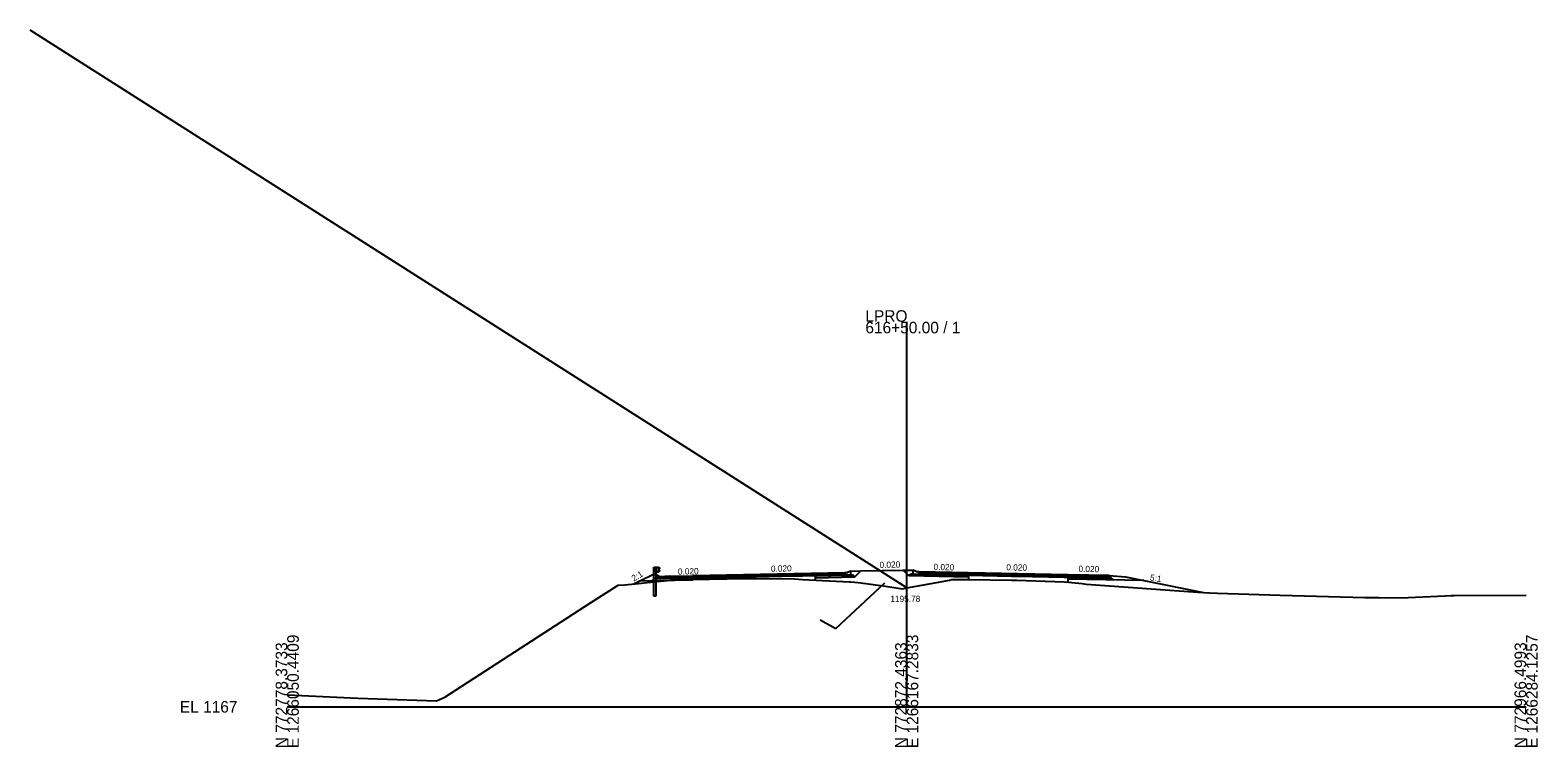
# Model space of a CAD drawing. Extents: x -3833 to 1267678, y -522 to 773248.
# Drawn here: x 1937.8 to 2302.8, y 7490.3 to 7663.8 of the extents above; entities that cross this region are included whole.
import ezdxf

# ---------------------------------------------------------------- set-up
doc = ezdxf.new("R2010")
doc.units = 0
for name, color, linetype in [('Exist Cross Section Cell', 7, 'Continuous'), ('Exist XS Center Line Elevation Label', 7, 'Continuous'), ('Exist XS Ground Line', 7, 'Continuous'), ('Prop CMT DNC', 7, 'Continuous'), ('Prop CMT Guardrail Graphics', 7, 'Continuous'), ('Prop CMT Pvmt Course 1', 7, 'Continuous'), ('Prop CMT Pvmt Course 2', 7, 'Continuous'), ('Prop CMT Pvmt Course 3', 7, 'Continuous'), ('Prop CMT Pvmt Course 4', 7, 'Continuous'), ('Prop CMT Shld Paved Course 1', 7, 'Continuous'), ('Prop CMT Shld Paved Course 2', 7, 'Continuous'), ('Prop CMT Shld Paved Course 4', 7, 'Continuous'), ('Prop CMT Slope Grass', 7, 'Continuous'), ('Prop CMT Subgrade Earthwork', 7, 'Continuous'), ('Prop Conc Curb and Gutter', 7, 'Continuous'), ('Prop Conc Island Cover', 7, 'Continuous'), ('Prop Corridor Mesh Bottom', 7, 'Continuous'), ('Prop XS Ditch Slope Text', 7, 'Continuous'), ('Prop XS Finish Grade', 7, 'Continuous'), ('Prop XS SE Text', 7, 'Continuous'), ('Scratch_Level_1', 7, 'Continuous'), ('Scratch_Level_5', 7, 'Continuous'), ('Typical Curb CELL', 7, 'Continuous')]:
    doc.layers.add(name, color=color, linetype=linetype)

msp = doc.modelspace()

# ---------------------------------------------------------------- linework, layer by layer
at = {"layer": 'Exist Cross Section Cell'}
for p, q in [((2150, 7500), (2150, 7593.23)), ((2000, 7500), (2150, 7500)), ((2150, 7500), (2300, 7500))]:
    msp.add_line(p, q, dxfattribs=at)
at = {"layer": 'Exist XS Ground Line'}
for p, q in [((2073.43, 7525.14), (2080.16, 7529.42)), ((2080.16, 7529.42), (2081.75, 7529.55)), ((2081.75, 7529.55), (2085.06, 7529.88)), ((2085.06, 7529.88), (2087.18, 7530.1)), ((2087.18, 7530.1), (2093.69, 7530.75)), ((2093.69, 7530.75), (2096.2, 7530.83)), ((2096.2, 7530.83), (2098.17, 7530.86)), ((2098.17, 7530.86), (2110.53, 7531.06)), ((2110.53, 7531.06), (2111.14, 7531.08)), ((2111.14, 7531.08), (2113.57, 7531.05)), ((2113.57, 7531.05), (2122.82, 7530.96)), ((2122.82, 7530.96), (2124.76, 7530.86)), ((2124.76, 7530.86), (2136.12, 7530.3)), ((2136.12, 7530.3), (2136.49, 7530.27)), ((2136.49, 7530.27), (2138.27, 7530.12)), ((2138.27, 7530.12), (2138.92, 7530)), ((2138.92, 7530), (2144.84, 7529.18)), ((2144.84, 7529.18), (2149.02, 7528.6)), ((2149.02, 7528.6), (2150, 7528.78)), ((2150, 7528.78), (2155.92, 7529.86)), ((2155.92, 7529.86), (2160.39, 7530.66)), ((2160.39, 7530.66), (2160.97, 7530.81)), ((2160.97, 7530.81), (2164.4, 7530.82)), ((2164.4, 7530.82), (2165, 7530.81)), ((2165, 7530.81), (2175.41, 7530.68)), ((2175.41, 7530.68), (2176.71, 7530.67)), ((2176.71, 7530.67), (2188.12, 7530.23)), ((2188.12, 7530.23), (2189.3, 7530.19)), ((2189.3, 7530.19), (2190.01, 7530.12)), ((2190.01, 7530.12), (2192.48, 7529.87)), ((2192.48, 7529.87), (2193.5, 7529.68)), ((2193.5, 7529.68), (2220.48, 7527.76)), ((2038.15, 7502.36), (2073.43, 7525.14)), ((2220.48, 7527.76), (2223.36, 7527.58)), ((2223.36, 7527.58), (2225.3, 7527.54)), ((2225.3, 7527.54), (2240.43, 7527.06)), ((2240.43, 7527.06), (2260.94, 7526.45)), ((2260.94, 7526.45), (2264.36, 7526.44)), ((2264.36, 7526.44), (2269.66, 7526.36)), ((2269.66, 7526.36), (2280.42, 7526.84)), ((2280.42, 7526.84), (2281.81, 7526.92)), ((2281.81, 7526.92), (2282.57, 7526.96)), ((2282.57, 7526.96), (2300, 7527.06)), ((2000, 7502.87), (2003.55, 7502.7)), ((2003.55, 7502.7), (2017.11, 7502.13)), ((2017.11, 7502.13), (2036.18, 7501.46)), ((2036.18, 7501.46), (2038.15, 7502.36))]:
    msp.add_line(p, q, dxfattribs=at)
at = {"layer": 'Prop CMT Guardrail Graphics'}
for p, q in [((2088.79, 7531.32), (2088.79, 7533.82)), ((2088.79, 7533.82), (2089.27, 7533.82)), ((2089.27, 7532.64), (2089.27, 7533.82)), ((2089.27, 7533.82), (2089.94, 7533.82)), ((2089.27, 7533.82), (2089.27, 7531.31)), ((2089.94, 7532.64), (2089.27, 7532.64)), ((2089.94, 7533.82), (2089.94, 7532.64)), ((2089.94, 7533.74), (2090.04, 7533.72)), ((2089.94, 7532.72), (2089.94, 7533.74)), ((2089.94, 7533.74), (2089.94, 7533.74)), ((2089.94, 7533.74), (2089.94, 7533.74)), ((2090.04, 7532.74), (2089.94, 7532.72)), ((2090.18, 7533.48), (2089.95, 7533.27)), ((2089.95, 7533.27), (2089.95, 7533.27)), ((2089.95, 7533.27), (2089.95, 7533.18)), ((2089.95, 7533.18), (2089.95, 7533.18)), ((2089.95, 7533.18), (2090.18, 7532.98)), ((2090.04, 7533.72), (2090.04, 7533.72)), ((2090.04, 7533.72), (2090.18, 7533.62)), ((2090.18, 7532.84), (2090.04, 7532.74)), ((2090.04, 7532.7), (2090.04, 7532.7)), ((2090.18, 7533.62), (2090.18, 7533.62)), ((2090.18, 7533.62), (2090.18, 7533.48)), ((2090.18, 7533.48), (2090.18, 7533.48)), ((2090.18, 7532.98), (2090.18, 7532.84)), ((2090.18, 7532.95), (2090.18, 7532.95)), ((2090.18, 7532.8), (2090.18, 7532.8)), ((2088.79, 7526.81), (2088.79, 7531.32)), ((2089.27, 7531.31), (2089.27, 7526.81)), ((2089.27, 7526.81), (2088.79, 7526.81))]:
    msp.add_line(p, q, dxfattribs=at)
at = {"layer": 'Prop CMT Pvmt Course 1'}
for p, q in [((2135, 7532.45), (2098.21, 7531.71)), ((2098.21, 7531.46), (2135, 7532.2)), ((2135, 7532.2), (2135, 7532.45)), ((2135, 7532.2), (2135, 7532.2)), ((2189, 7531.97), (2165, 7532.45)), ((2165, 7532.45), (2165, 7532.2)), ((2165, 7532.2), (2165, 7532.2)), ((2189, 7531.72), (2189, 7531.97)), ((2189, 7531.97), (2189, 7531.97)), ((2098.21, 7531.46), (2111, 7531.72)), ((2098.21, 7531.71), (2098.21, 7531.71)), ((2098.21, 7531.71), (2098.21, 7531.46)), ((2098.21, 7531.46), (2098.21, 7531.46)), ((2189, 7531.72), (2189, 7531.72)), ((2189, 7531.72), (2189, 7531.72))]:
    msp.add_line(p, q, dxfattribs=at)
at = {"layer": 'Prop CMT Pvmt Course 2'}
for p, q in [((2135, 7532.2), (2135, 7532.2)), ((2135, 7532.2), (2135, 7531.87)), ((2135, 7531.87), (2135, 7531.87)), ((2135, 7531.87), (2135, 7531.86)), ((2135, 7531.86), (2135, 7531.86)), ((2165, 7532.2), (2153, 7532.44)), ((2153, 7532.1), (2165, 7531.86)), ((2165, 7532.2), (2165, 7532.2)), ((2165, 7531.86), (2165, 7531.86)), ((2165, 7531.86), (2165, 7531.86)), ((2165, 7531.86), (2165, 7531.86))]:
    msp.add_line(p, q, dxfattribs=at)
at = {"layer": 'Prop CMT Pvmt Course 3'}
for p, q in [((2137.01, 7531.9), (2135, 7531.86)), ((2137.46, 7531.45), (2137.01, 7531.9)), ((2150.7, 7531.86), (2150.99, 7532.14))]:
    msp.add_line(p, q, dxfattribs=at)
at = {"layer": 'Prop CMT Pvmt Course 4'}
for p, q in [((2127.86, 7532.3), (2127.86, 7530.71)), ((2135, 7531.86), (2135, 7531.87)), ((2135, 7531.86), (2135, 7531.86)), ((2150.99, 7532.14), (2150.54, 7531.7)), ((2151.49, 7532.13), (2150.99, 7532.14)), ((2165, 7531.4), (2165, 7531.86)), ((2165, 7531.86), (2165, 7531.86)), ((2165, 7531.86), (2165, 7531.86)), ((2137.46, 7531.45), (2127.86, 7531.26)), ((2165, 7531.03), (2165, 7531.03)), ((2165, 7531.03), (2165, 7531.03)), ((2165, 7531.03), (2165, 7531.03))]:
    msp.add_line(p, q, dxfattribs=at)
at = {"layer": 'Prop CMT Shld Paved Course 1'}
for p, q in [((2135, 7532.45), (2135, 7532.45)), ((2135, 7532.45), (2135, 7532.2)), ((2135, 7532.2), (2135, 7532.2)), ((2135, 7532.2), (2135, 7532.2)), ((2165, 7532.45), (2153, 7532.69)), ((2165, 7532.2), (2165, 7532.45)), ((2165, 7532.45), (2165, 7532.45)), ((2165, 7532.2), (2165, 7532.2)), ((2165, 7532.2), (2165, 7532.2)), ((2189, 7531.97), (2189, 7530.93)), ((2199, 7531.77), (2189, 7531.97)), ((2089.95, 7531.26), (2089.95, 7531.26)), ((2089.95, 7531.26), (2089.95, 7531.26)), ((2089.95, 7531.26), (2089.95, 7531.26)), ((2089.95, 7531.26), (2089.95, 7531.26)), ((2090.21, 7531.51), (2090.21, 7531.51)), ((2090.21, 7531.51), (2090.21, 7531.51)), ((2092.54, 7531.6), (2098.21, 7531.71)), ((2098.21, 7531.46), (2093.95, 7531.37)), ((2098.21, 7531.71), (2098.21, 7531.46)), ((2189, 7531.72), (2199.26, 7531.51)), ((2199.26, 7531.51), (2199, 7531.77))]:
    msp.add_line(p, q, dxfattribs=at)
at = {"layer": 'Prop CMT Shld Paved Course 2'}
for p, q in [((2113.57, 7531.77), (2122.82, 7531.95)), ((2122.82, 7531.95), (2124.76, 7531.99)), ((2122.82, 7531.95), (2122.82, 7531.95)), ((2124.76, 7531.99), (2135, 7532.2)), ((2124.76, 7531.99), (2124.76, 7531.99)), ((2135, 7531.86), (2124.76, 7531.66)), ((2135, 7532.2), (2135, 7532.2)), ((2135, 7532.2), (2135, 7531.86)), ((2135, 7531.86), (2135, 7531.86)), ((2135, 7531.86), (2135, 7531.86)), ((2175.41, 7531.99), (2165, 7532.2)), ((2165, 7532.2), (2165, 7532.2)), ((2165, 7532.2), (2165, 7532.2)), ((2165, 7532.2), (2165, 7532.2)), ((2165, 7532.2), (2165, 7531.86)), ((2165, 7531.86), (2165, 7531.86)), ((2165, 7531.86), (2165, 7531.86)), ((2165, 7531.86), (2165, 7531.86)), ((2165, 7531.86), (2165, 7531.86)), ((2165, 7531.86), (2175.41, 7531.65)), ((2176.71, 7531.96), (2175.41, 7531.99)), ((2175.41, 7531.99), (2175.41, 7531.99)), ((2188.12, 7531.73), (2176.71, 7531.96)), ((2176.71, 7531.96), (2176.71, 7531.96)), ((2089.61, 7530.92), (2089.61, 7530.92)), ((2089.61, 7530.92), (2089.61, 7530.92)), ((2089.61, 7530.92), (2089.61, 7530.92)), ((2089.61, 7530.92), (2089.61, 7530.92)), ((2089.95, 7531.26), (2089.95, 7531.26)), ((2089.95, 7531.26), (2089.95, 7531.26)), ((2092.54, 7531.35), (2098.21, 7531.46)), ((2098.21, 7531.13), (2092.54, 7531.01)), ((2098.21, 7531.46), (2111.14, 7531.72)), ((2098.21, 7531.13), (2098.21, 7531.46)), ((2098.21, 7531.46), (2098.21, 7531.13)), ((2111.14, 7531.39), (2098.21, 7531.13)), ((2098.21, 7531.13), (2098.21, 7531.13)), ((2111.14, 7531.72), (2113.57, 7531.77)), ((2111.14, 7531.72), (2111.14, 7531.72)), ((2113.57, 7531.43), (2111.14, 7531.39)), ((2111.14, 7531.39), (2111.14, 7531.39)), ((2113.57, 7531.77), (2113.57, 7531.77)), ((2122.82, 7531.62), (2113.57, 7531.43)), ((2113.57, 7531.43), (2113.57, 7531.43)), ((2124.76, 7531.66), (2122.82, 7531.62)), ((2122.82, 7531.62), (2122.82, 7531.62)), ((2124.76, 7531.66), (2124.76, 7531.66)), ((2175.41, 7531.65), (2175.41, 7531.65)), ((2175.41, 7531.65), (2176.71, 7531.63)), ((2176.71, 7531.63), (2176.71, 7531.63)), ((2176.71, 7531.63), (2188.12, 7531.4)), ((2189, 7531.72), (2188.12, 7531.73)), ((2188.12, 7531.73), (2188.12, 7531.73)), ((2188.12, 7531.4), (2188.12, 7531.4)), ((2188.12, 7531.4), (2189, 7531.38)), ((2199.26, 7531.51), (2189, 7531.72)), ((2189, 7531.39), (2199.59, 7531.17)), ((2189, 7531.38), (2189, 7531.38)), ((2199.59, 7531.17), (2199.26, 7531.51))]:
    msp.add_line(p, q, dxfattribs=at)
at = {"layer": 'Prop CMT Shld Paved Course 4'}
for p, q in [((2088.3, 7530.47), (2089.01, 7531.18)), ((2089.01, 7531.18), (2089.52, 7531.18)), ((2092.54, 7531.18), (2092.54, 7531.02)), ((2098.21, 7530.67), (2093.15, 7530.57)), ((2093.61, 7531.03), (2094.11, 7531.04)), ((2094.11, 7531.04), (2098.21, 7531.13)), ((2098.21, 7531.13), (2098.21, 7530.67)), ((2199.09, 7531.18), (2189, 7531.39)), ((2199.59, 7531.17), (2199.09, 7531.18)), ((2200.06, 7530.71), (2199.59, 7531.17))]:
    msp.add_line(p, q, dxfattribs=at)
at = {"layer": 'Prop CMT Slope Grass'}
for p, q in [((2085.23, 7530.41), (2088.82, 7532.21)), ((2088.82, 7532.21), (2089.52, 7531.86)), ((2136.51, 7532.88), (2138.92, 7532.92)), ((2149.16, 7533.08), (2151.49, 7533.12)), ((2199, 7531.77), (2203, 7531.45)), ((2203, 7531.45), (2207.43, 7530.56))]:
    msp.add_line(p, q, dxfattribs=at)
at = {"layer": 'Prop CMT Subgrade Earthwork'}
for p, q in [((2137.46, 7531.45), (2138.92, 7532.92)), ((2150.54, 7531.7), (2149.16, 7533.08)), ((2098.21, 7530.67), (2085.23, 7530.41)), ((2098.21, 7530.67), (2098.21, 7530.86)), ((2127.86, 7531.26), (2137.46, 7531.45)), ((2127.86, 7531.26), (2127.86, 7530.71)), ((2165, 7531.4), (2150.54, 7531.7)), ((2165, 7531.4), (2165, 7530.81)), ((2207.43, 7530.56), (2189, 7530.93)), ((2189, 7530.93), (2189, 7530.2))]:
    msp.add_line(p, q, dxfattribs=at)
at = {"layer": 'Prop Conc Curb and Gutter'}
for p, q in [((2135.75, 7532.46), (2135, 7532.45)), ((2135, 7532.45), (2135, 7532.45)), ((2135, 7532.45), (2135, 7531.86)), ((2135, 7531.86), (2136.51, 7531.89)), ((2135, 7531.86), (2135, 7531.86)), ((2135, 7531.86), (2135, 7531.86)), ((2136.51, 7532.88), (2135.75, 7532.63)), ((2135.75, 7532.63), (2135.75, 7532.63)), ((2135.75, 7532.63), (2135.75, 7532.46)), ((2135.75, 7532.46), (2135.75, 7532.46)), ((2136.51, 7531.89), (2136.51, 7532.88)), ((2136.51, 7531.89), (2136.51, 7531.89)), ((2152.25, 7532.87), (2151.49, 7533.12)), ((2151.49, 7533.12), (2151.49, 7532.13)), ((2151.49, 7532.13), (2151.49, 7532.13)), ((2151.49, 7532.13), (2153, 7532.1)), ((2152.25, 7532.7), (2152.25, 7532.87)), ((2152.25, 7532.87), (2152.25, 7532.87)), ((2153, 7532.68), (2152.25, 7532.7)), ((2152.25, 7532.7), (2152.25, 7532.7)), ((2153, 7532.1), (2153, 7532.68)), ((2153, 7532.68), (2153, 7532.68)), ((2153, 7532.1), (2153, 7532.1)), ((2153, 7532.1), (2153, 7532.1))]:
    msp.add_line(p, q, dxfattribs=at)
at = {"layer": 'Prop Conc Island Cover'}
for p, q in [((2151.49, 7533.12), (2151.49, 7533.12)), ((2151.49, 7532.87), (2151.49, 7532.87))]:
    msp.add_line(p, q, dxfattribs=at)
at = {"layer": 'Prop Corridor Mesh Bottom'}
msp.add_line((2135, 7532.45), (2135, 7532.2), dxfattribs=at)
at = {"layer": 'Prop XS Finish Grade'}
for p, q in [((2138.92, 7532.92), (2149.16, 7533.08)), ((2083.96, 7529.77), (2085.23, 7530.41)), ((2207.43, 7530.56), (2221.85, 7527.68))]:
    msp.add_line(p, q, dxfattribs=at)
at = {"layer": 'Scratch_Level_1'}
msp.add_line((2150, 7528.78), (1937.75, 7663.84), dxfattribs=at)
at = {"layer": 'Scratch_Level_5'}
for p, q in [((2132.86, 7518.95), (2144.72, 7529.98)), ((2132.86, 7518.95), (2144.72, 7529.98)), ((2129.08, 7521.06), (2132.86, 7518.95)), ((2129.08, 7521.06), (2132.86, 7518.95))]:
    msp.add_line(p, q, dxfattribs=at)
at = {"layer": 'Typical Curb CELL'}
for p, q in [((2089.52, 7531.18), (2089.52, 7531.86)), ((2090.21, 7531.51), (2089.52, 7531.86)), ((2089.52, 7531.18), (2092.54, 7531.18)), ((2089.56, 7531.48), (2089.71, 7531.52)), ((2089.69, 7531.43), (2089.56, 7531.48)), ((2089.71, 7531.52), (2089.69, 7531.43)), ((2090.22, 7531.4), (2090.12, 7531.32)), ((2090.12, 7531.32), (2090.29, 7531.28)), ((2092.53, 7531.6), (2090.21, 7531.51)), ((2090.29, 7531.28), (2090.22, 7531.4)), ((2090.97, 7531.45), (2090.93, 7531.34)), ((2090.93, 7531.34), (2091.05, 7531.33)), ((2091.05, 7531.33), (2090.97, 7531.45)), ((2091.47, 7531.4), (2091.37, 7531.32)), ((2091.37, 7531.32), (2091.54, 7531.28)), ((2091.54, 7531.28), (2091.47, 7531.4)), ((2092.22, 7531.45), (2092.18, 7531.34)), ((2092.18, 7531.34), (2092.3, 7531.33)), ((2092.3, 7531.33), (2092.22, 7531.45)), ((2092.54, 7531.6), (2092.54, 7531.6)), ((2092.54, 7531.18), (2092.54, 7531.59))]:
    msp.add_line(p, q, dxfattribs=at)
for centre in [(2089.58, 7531.56), (2089.68, 7531.29), (2089.8, 7531.34), (2090.06, 7531.37), (2090.07, 7531.32), (2090.25, 7531.23), (2090.28, 7531.34), (2090.47, 7531.3), (2090.52, 7531.41), (2090.65, 7531.38), (2090.68, 7531.26), (2090.74, 7531.29), (2090.93, 7531.29), (2091.05, 7531.34), (2091.14, 7531.33), (2091.24, 7531.29), (2091.3, 7531.43), (2091.31, 7531.37), (2091.32, 7531.32), (2091.53, 7531.34), (2091.72, 7531.3), (2091.77, 7531.41), (2091.82, 7531.38), (2091.9, 7531.38), (2091.93, 7531.26), (2091.98, 7531.29), (2092.04, 7531.47), (2092.41, 7531.54), (2092.45, 7531.42)]:
    msp.add_circle(centre, 0.00802, dxfattribs=at)
msp.add_arc((2092.53, 7531.59), 0.0104, 0, 92.048, dxfattribs=at)

# ---------------------------------------------------------------- texts
at = {"layer": 'Exist Cross Section Cell'}
for s, p in [('LPRO', (2140, 7593.23)), ('616+50.00 / 1', (2140, 7590.43)), ('EL 1167', (1974, 7498.6))]:
    msp.add_text(s, height=2.8, dxfattribs=at).set_placement(p)
for s, p in [('E 1266050.4409', (2002.8, 7490)), ('E 1266167.2833', (2152.8, 7490)), ('E 1266284.1257', (2302.8, 7490)), ('N 772778.3733', (2000, 7490)), ('N 772872.4363', (2150, 7490)), ('N 772966.4993', (2300, 7490))]:
    msp.add_text(s, height=2.8, rotation=90, dxfattribs=at).set_placement(p)
at = {"layer": 'Exist XS Center Line Elevation Label'}
msp.add_text('1195.78', height=1.5, dxfattribs=at).set_placement((2146.05, 7525.39))
at = {"layer": 'Prop CMT DNC'}
for p in [(2111, 7531.97), (2135, 7532.45), (2135, 7532.45), (2135.75, 7532.46), (2152.25, 7532.7), (2165, 7532.45), (2165, 7532.45), (2189, 7531.97), (2189, 7531.97)]:
    msp.add_text('X', height=0.00025, dxfattribs=at).set_placement(p)
at = {"layer": 'Prop XS Ditch Slope Text'}
for s, rotation, p in [('2:1', 30.3353, (2083.92, 7530.31)), ('5:1', 350.6965, (2208.83, 7530.62))]:
    msp.add_text(s, height=1.5, rotation=rotation, dxfattribs=at).set_placement(p)
at = {"layer": 'Prop XS SE Text'}
for rotation, p in [(1.397, (2094.63, 7531.99)), (1.397, (2117.15, 7532.68)), (1.299, (2143.44, 7533.61)), (358.8542, (2156.49, 7533.13)), (358.8542, (2174.12, 7533.05)), (358.8542, (2191.59, 7532.68))]:
    msp.add_text('0.020', height=1.5, rotation=rotation, dxfattribs=at).set_placement(p)

doc.saveas('drawing.dxf')
